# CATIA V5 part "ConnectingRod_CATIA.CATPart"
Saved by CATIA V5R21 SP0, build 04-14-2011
Part number: ConnectingRod
Bounding box of the stored display mesh (mm): x -5 to 170, y -5 to 10, z 0 to 10
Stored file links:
  C:\Users\DHARUN\Documents\Codex\2026-11-26\task-2-structural-simulation-fea-perform\outputs\task3_slider_crank\ConnectingRod_CATIA.CATPart
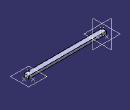
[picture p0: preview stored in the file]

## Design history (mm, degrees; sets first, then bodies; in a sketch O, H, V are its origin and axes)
Set1 "KinematicReferences"
  Point1 "O": (0, 0, 0)
  Point2 "Z": (0, 0, 10)
  Point3 "X": (10, 0, 0)
  Point4 "Y": (0, 10, 0)
  Line1: type PtPt, FirstPoint Point1, SecondPoint Point2
  Plane1: type 3Points, Element1 Point1, Element2 Point3, Element3 Point4
  Point5 "PinO": (160, 0, 0)
  Point6 "PinZ": (160, 0, 10)
  Point7 "PinX": (170, 0, 0)
  Point8 "PinY": (160, 10, 0)
  Line2: type PtPt, FirstPoint Point5, SecondPoint Point6
  Plane2: type 3Points, Element1 Point5, Element2 Point7, Element3 Point8
Body1 (main body)
  Sketch1 on xy-plane, origin (0, 0, 0), H (1, 0, 0), V (0, 1, 0)
    line L1 (-5, -5) -> (165, -5)
    line L2 (165, -5) -> (165, 5)
    line L3 (165, 5) -> (-5, 5)
    line L4 (-5, 5) -> (-5, -5)
    point P1 (-5, -5)
    point P2 (165, -5)
    point P3 (165, -5)
    point P4 (165, 5)
    point P5 (165, 5)
    point P6 (-5, 5)
    point P7 (-5, 5)
    point P8 (-5, -5)
    coincidence: P1 P8, P2 P3, P4 P5, P6 P7
  Pad1 "ConnectingRod_Solid": profile Sketch1, direction (0, 0, 1), length 6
